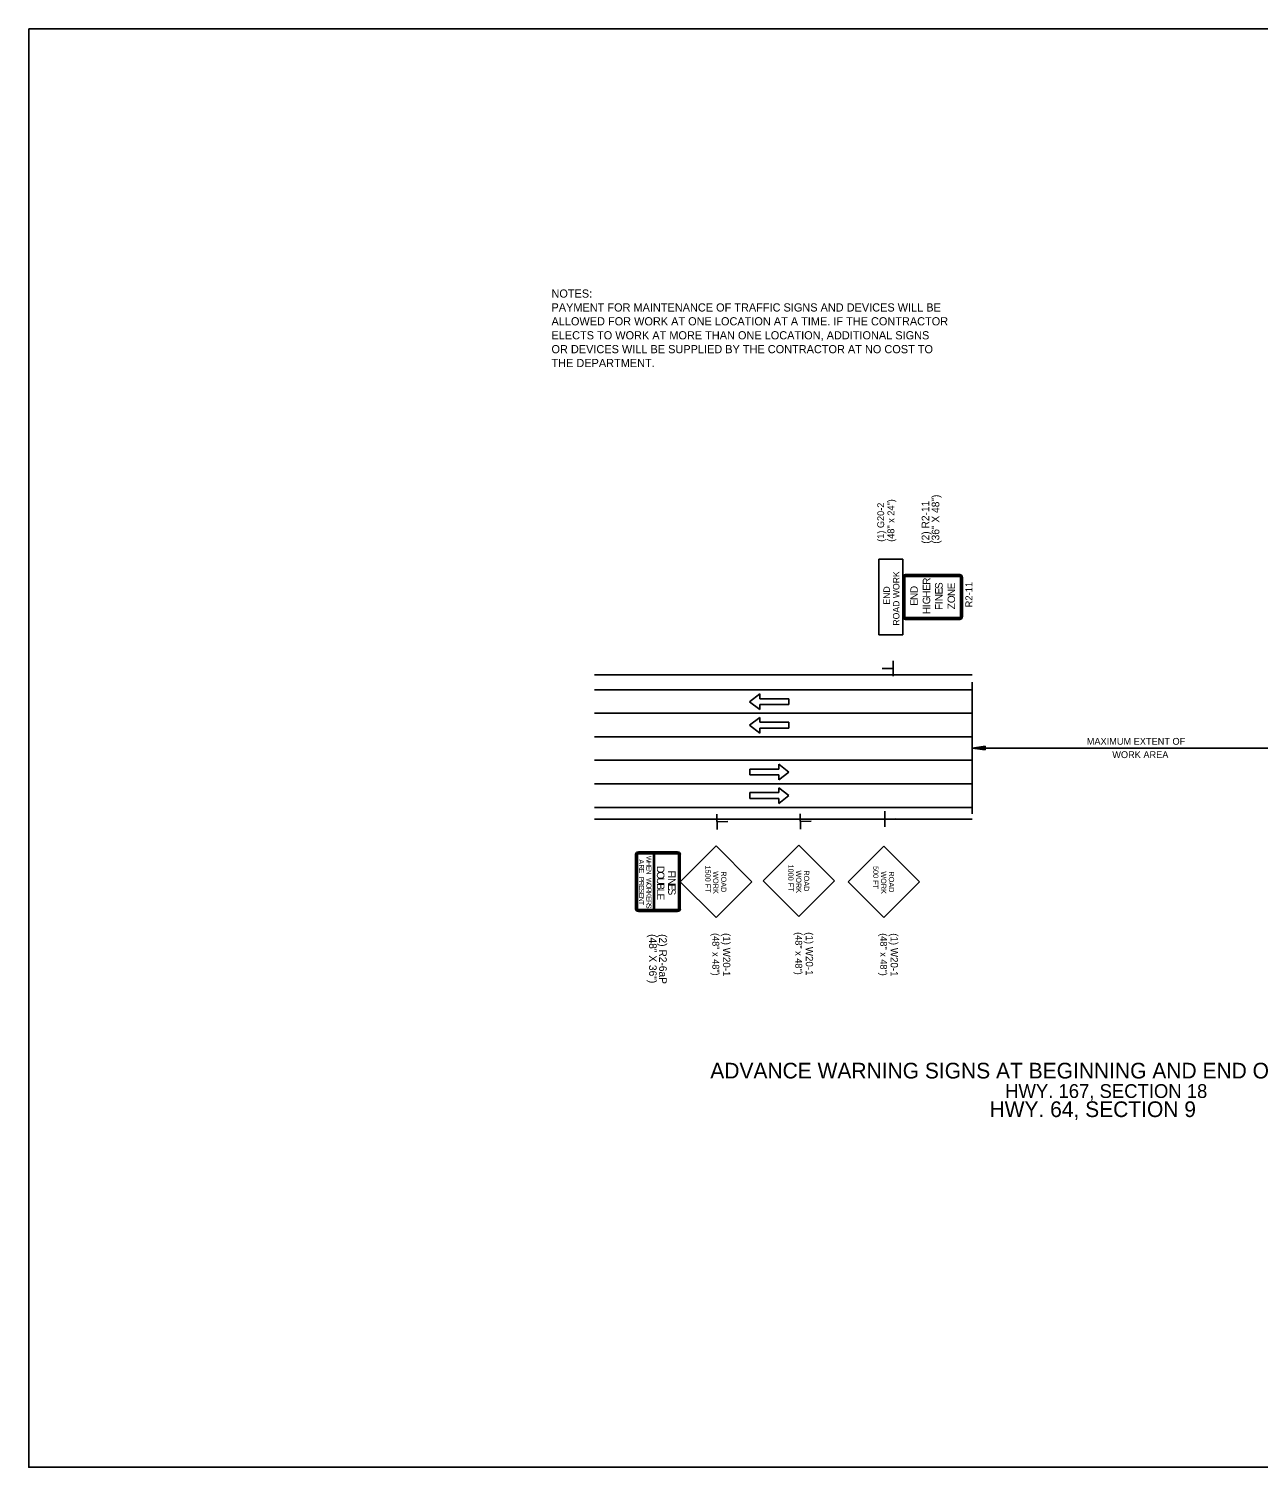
# Model space of a CAD drawing. Extents: x 32485 to 39285, y 55121 to 58033.
# Drawn here: x 37580 to 38520, y 55121 to 56221 of the extents above; entities that cross this region are included whole.
import ezdxf

# ---------------------------------------------------------------- set-up
doc = ezdxf.new("R2010")
doc.units = 0
for name, color, linetype in [('Default', 7, 'Continuous'), ('DSN_DRFT_Junk-No-Plot', 7, 'Continuous'), ('R_Border', 7, 'Continuous'), ('R_Draft', 7, 'Continuous'), ('R_Exist Surface', 7, 'Continuous')]:
    doc.layers.add(name, color=color, linetype=linetype)

msp = doc.modelspace()

# ---------------------------------------------------------------- linework, layer by layer
at = {"layer": 'Default'}
for p, q in [((38291.6, 55803.4), (38250.2, 55803.4)), ((38248, 55801.2), (38248, 55771.2)), ((38248.6, 55801.2), (38248.6, 55771.2)), ((38249.5, 55771.2), (38249.5, 55801.2)), ((38291.6, 55802.8), (38250.2, 55802.8)), ((38250.2, 55801.9), (38291.6, 55801.9)), ((38292.3, 55801.2), (38292.3, 55771.2)), ((38293.1, 55771.2), (38293.1, 55801.2)), ((38293.7, 55771.2), (38293.7, 55801.2)), ((38291.6, 55770.5), (38250.2, 55770.5)), ((38250.2, 55769.7), (38291.6, 55769.7)), ((38250.2, 55769.1), (38291.6, 55769.1)), ((38301, 55721), (38301, 55620.4)), ((38131, 55706.1), (38138.8, 55712.1)), ((38138.8, 55700.1), (38131, 55706.1)), ((38138.8, 55708.4), (38138.8, 55712.1)), ((38138.8, 55708.4), (38160.9, 55708.4)), ((38160.9, 55703.9), (38160.9, 55708.4)), ((38131, 55688.1), (38138.8, 55694.1)), ((38138.8, 55703.9), (38160.9, 55703.9)), ((38138.8, 55700.1), (38138.8, 55703.9)), ((38138.8, 55690.4), (38138.8, 55694.1)), ((38138.8, 55682.1), (38131, 55688.1)), ((38138.8, 55690.4), (38160.9, 55690.4)), ((38138.8, 55685.9), (38160.9, 55685.9)), ((38138.8, 55682.1), (38138.8, 55685.9)), ((38160.9, 55685.9), (38160.9, 55690.4)), ((38301, 55670.7), (38558.8, 55670.7)), ((38357.1, 55670.7), (38502.8, 55670.7)), ((38153.2, 55654.6), (38131.2, 55654.6)), ((38131.2, 55654.6), (38131.2, 55650.1)), ((38153.2, 55650.1), (38131.2, 55650.1)), ((38153.2, 55658.3), (38153.2, 55654.6)), ((38153.2, 55658.3), (38161, 55652.3)), ((38161, 55652.3), (38153.2, 55646.3)), ((38153.2, 55650.1), (38153.2, 55646.3)), ((38153.2, 55640.3), (38153.2, 55636.6)), ((38153.2, 55640.3), (38161, 55634.3)), ((38153.2, 55636.6), (38131.2, 55636.6)), ((38131.2, 55636.6), (38131.2, 55632.1)), ((38153.2, 55632.1), (38131.2, 55632.1)), ((38161, 55634.3), (38153.2, 55628.3)), ((38153.2, 55632.1), (38153.2, 55628.3)), ((38043.8, 55589.2), (38043.8, 55547.8)), ((38044.4, 55589.2), (38044.4, 55547.8)), ((38045.2, 55547.8), (38045.2, 55589.2)), ((38075.9, 55591.3), (38045.9, 55591.3)), ((38075.9, 55590.7), (38045.9, 55590.7)), ((38045.9, 55589.9), (38075.9, 55589.9)), ((38057.4, 55547.1), (38057.4, 55589.9)), ((38057.4, 55589.9), (38058.2, 55589.9)), ((38058.2, 55589.9), (38058.2, 55547.1)), ((38076.6, 55589.2), (38076.6, 55547.8)), ((38077.4, 55547.8), (38077.4, 55589.2)), ((38078, 55547.8), (38078, 55589.2)), ((38075.9, 55547.1), (38045.9, 55547.1)), ((38045.9, 55546.2), (38075.9, 55546.2)), ((38045.9, 55545.6), (38075.9, 55545.6)), ((38058.2, 55547.1), (38057.4, 55547.1))]:
    msp.add_line(p, q, dxfattribs=at)
msp.add_lwpolyline([(37579.9, 56220.7), (37579.9, 55120.7), (39279.9, 55120.7), (39279.9, 56220.7)], close=True, dxfattribs=at)
for centre, radius, start, end in [((38250.2, 55801.2), 2.14, 90, 180), ((38291.6, 55801.2), 2.14, 0, 90), ((38250.2, 55801.2), 1.55, 90, 180), ((38250.2, 55801.2), 0.714, 90, 180), ((38291.6, 55801.2), 1.55, 0, 90), ((38291.6, 55801.2), 0.714, 0, 90), ((38250.2, 55771.2), 2.14, 180, 270), ((38250.2, 55771.2), 1.55, 180, 270), ((38250.2, 55771.2), 0.714, 180, 270), ((38291.6, 55771.2), 2.14, 270, 0), ((38291.6, 55771.2), 1.55, 270, 0), ((38291.6, 55771.2), 0.714, 270, 0), ((38045.9, 55589.2), 2.14, 90, 180), ((38045.9, 55589.2), 1.55, 90, 180), ((38045.9, 55589.2), 0.714, 90, 180), ((38075.9, 55589.2), 2.14, 0, 90), ((38075.9, 55589.2), 1.55, 0, 90), ((38075.9, 55589.2), 0.714, 0, 90), ((38045.9, 55547.8), 2.14, 180, 270), ((38045.9, 55547.8), 1.55, 180, 270), ((38045.9, 55547.8), 0.714, 180, 270), ((38075.9, 55547.8), 2.14, 270, 0), ((38075.9, 55547.8), 1.55, 270, 0), ((38075.9, 55547.8), 0.714, 270, 0)]:
    msp.add_arc(centre, radius, start, end, dxfattribs=at)
at = {"layer": 'DSN_DRFT_Junk-No-Plot'}
msp.add_lwpolyline([(37579.9, 56220.7), (39279.9, 56220.7), (39279.9, 55120.7), (37579.9, 55120.7)], close=True, dxfattribs=at)
at = {"layer": 'R_Border'}
for p, q in [((38229.8, 55815.2), (38229.8, 55757.3)), ((38248, 55815.2), (38229.8, 55815.2)), ((38248, 55815.2), (38248, 55757.3)), ((38248, 55757.3), (38229.8, 55757.3)), ((38240.6, 55737.4), (38240.6, 55725.6)), ((38240.4, 55731.6), (38232.4, 55731.5)), ((38106.1, 55608.4), (38105.9, 55620.1)), ((38169.8, 55608.7), (38169.6, 55620.4)), ((38234.4, 55610.5), (38234.3, 55622.3)), ((38234.5, 55616.4), (38242.6, 55616.5)), ((38106.2, 55614.2), (38114.2, 55614.4)), ((38169.8, 55614.5), (38177.9, 55614.7)), ((38078, 55568.5), (38105.3, 55595.8)), ((38132.6, 55568.5), (38105.3, 55595.8)), ((38141.4, 55569.2), (38168.6, 55596.5)), ((38195.9, 55569.2), (38168.6, 55596.5)), ((38206.3, 55568.4), (38233.5, 55595.7)), ((38260.8, 55568.4), (38233.5, 55595.7)), ((38105.3, 55541.2), (38078, 55568.5)), ((38105.3, 55541.2), (38132.6, 55568.5)), ((38168.6, 55541.9), (38141.4, 55569.2)), ((38168.6, 55541.9), (38195.9, 55569.2)), ((38233.5, 55541.1), (38206.3, 55568.4)), ((38233.5, 55541.1), (38260.8, 55568.4))]:
    msp.add_line(p, q, dxfattribs=at)
at = {"layer": 'R_Draft'}
for p, q in [((38311, 55672.2), (38301, 55670.7)), ((38311, 55672), (38302.7, 55670.7)), ((38311, 55671.7), (38304.4, 55670.7)), ((38311, 55671.5), (38306.1, 55670.7)), ((38311, 55671.2), (38307.8, 55670.7)), ((38311, 55669.2), (38311, 55672.2)), ((38311, 55669.2), (38301, 55670.7)), ((38311, 55669.5), (38302.7, 55670.7)), ((38311, 55669.7), (38304.4, 55670.7)), ((38311, 55670), (38306.1, 55670.7)), ((38311, 55670.2), (38307.8, 55670.7)), ((38311, 55671), (38309.5, 55670.7)), ((38311, 55670.5), (38309.5, 55670.7))]:
    msp.add_line(p, q, dxfattribs=at)
at = {"layer": 'R_Exist Surface'}
for p, q in [((38012.3, 55726.8), (38301, 55726.8)), ((38012.3, 55715.3), (38301, 55715.3)), ((38012.3, 55697.3), (38301, 55697.3)), ((38012.3, 55679.3), (38301, 55679.3)), ((38012.3, 55661.3), (38301, 55661.3)), ((38012.3, 55643.3), (38301, 55643.3)), ((38012.3, 55625.3), (38301, 55625.3)), ((38012.3, 55616.3), (38301, 55616.3))]:
    msp.add_line(p, q, dxfattribs=at)

# ---------------------------------------------------------------- texts
at = {"layer": 'Default'}
for s, height, p in [('NOTES: ', 6.25, (37979.5, 56015.1)), ('PAYMENT FOR MAINTENANCE OF TRAFFIC SIGNS AND DEVICES WILL BE ', 6.25, (37979.5, 56004.5)), ('ALLOWED FOR WORK AT ONE LOCATION AT A TIME. IF THE CONTRACTOR', 6.25, (37979.5, 55993.9)), ('ELECTS TO WORK AT MORE THAN ONE LOCATION, ADDITIONAL SIGNS', 6.25, (37979.5, 55983.2)), ('THE DEPARTMENT.', 6.25, (37979.5, 55962)), ('OR DEVICES WILL BE SUPPLIED BY THE CONTRACTOR AT NO COST TO ', 6.25, (37979.5, 55972.6)), ('MAXIMUM EXTENT OF ', 5.25, (38388.7, 55673.2)), ('WORK AREA', 5.25, (38408.2, 55663)), ('ADVANCE WARNING SIGNS AT BEGINNING AND END OF WORK ZONE', 12, (38100.9, 55418)), ('HWY. 167, SECTION 18', 10.557, (38326.3, 55403.1)), (' HWY. 64, SECTION 9 ', 12, (38309.9, 55388.5))]:
    msp.add_text(s, height=height, dxfattribs=at).set_placement(p)
for s, height, rotation, p in [('D', 5.71, 90, (38259.5, 55789.2)), ('R', 5.71, 90, (38269, 55795.5)), ('E', 5.71, 90, (38269, 55791)), ('S', 5.71, 90, (38278.5, 55792.3)), ('E', 5.71, 90, (38278.5, 55788.2)), ('E', 5.71, 90, (38288, 55792.1)), ('R2-11', 5.38, 90, (38301.3, 55778.2)), ('N', 5.71, 90, (38259.5, 55783.9)), ('E', 5.71, 90, (38259.5, 55779.4)), ('G', 5.71, 90, (38269, 55780.6)), ('H', 5.71, 90, (38269, 55785.7)), ('N', 5.71, 90, (38278.5, 55783)), ('I', 5.71, 90, (38278.5, 55780.7)), ('O', 5.71, 90, (38288, 55781.5)), ('N', 5.71, 90, (38288, 55786.9)), ('Z', 5.71, 90, (38288, 55776.8)), ('I', 5.71, 90, (38269, 55778.4)), ('H', 5.71, 90, (38269, 55773.1)), ('F', 5.71, 90, (38278.5, 55776.3)), ('A', 3.81, 270, (38046.4, 55585.5)), ('W', 3.81, 270, (38052.1, 55588.2)), ('H', 3.81, 270, (38052.1, 55584.2)), ('R', 3.81, 270, (38046.4, 55581.7)), ('E', 3.81, 270, (38046.4, 55578.5)), ('E', 3.81, 270, (38052.1, 55580.7)), ('N', 3.81, 270, (38052.1, 55577.7)), ('O', 5.71, 270, (38060.1, 55576.3)), ('D', 5.71, 270, (38060.1, 55580.5)), ('F', 5.71, 270, (38068.7, 55577)), ('I', 5.71, 270, (38068.7, 55573.3)), ('P', 3.81, 270, (38046.4, 55572.3)), ('R', 3.81, 270, (38046.4, 55569.2)), ('E', 3.81, 270, (38046.4, 55565.9)), ('S', 3.81, 270, (38046.4, 55563.2)), ('W', 3.81, 270, (38052.1, 55571.3)), ('O', 3.81, 270, (38052.1, 55567.4)), ('R', 3.81, 270, (38052.1, 55563.9)), ('U', 5.71, 270, (38060.1, 55571.7)), ('B', 5.71, 270, (38060.1, 55567.3)), ('L', 5.71, 270, (38060.1, 55563.1)), ('S', 5.71, 270, (38068.7, 55563.2)), ('N', 5.71, 270, (38068.7, 55571.2)), ('E', 5.71, 270, (38068.7, 55566.8)), ('E', 3.81, 270, (38046.4, 55560)), ('N', 3.81, 270, (38046.4, 55557)), ('T', 3.81, 270, (38046.4, 55553.8)), ('K', 3.81, 270, (38052.1, 55560.7)), ('E', 3.81, 270, (38052.1, 55557.4)), ('R', 3.81, 270, (38052.1, 55554.3)), ('S', 3.81, 270, (38052.1, 55551.4)), ('E', 5.71, 270, (38060.1, 55559.4))]:
    msp.add_text(s, height=height, rotation=rotation, dxfattribs=at).set_placement(p)
at = {"layer": 'R_Border'}
for s, height, rotation, p in [('(48" x 24")', 5.233, 90, (38241.6, 55828.4)), ('(1) G20-2', 5.23, 90, (38233.8, 55828.4)), ('ROAD WORK', 4.95, 90, (38245.5, 55764.3)), ('END', 4.95, 90, (38238.2, 55780.4)), ('1500 FT', 4.02, 270.0006, (38097.1, 55580.8)), ('WORK', 4.02, 270, (38103.1, 55576.5)), ('ROAD', 4.02, 270.0004, (38109.2, 55576.4)), ('1000 FT', 4.02, 270.0006, (38160.5, 55581.6)), ('WORK', 4.02, 270, (38166.5, 55577.1)), ('ROAD', 4.02, 270.0004, (38172.5, 55577.1)), (' 500 FT', 4.02, 270.0006, (38225.4, 55582)), ('WORK', 4.02, 270, (38231.4, 55576.4)), ('ROAD', 4.02, 270.0004, (38237.4, 55576.3)), ('(48" x 48")', 5.233, 270, (38102.5, 55529.2)), ('(1) W20-1', 5.58, 270, (38110.6, 55529.2)), ('(48" x 48")', 5.233, 270, (38165.9, 55529.9)), ('(1) W20-1', 5.58, 270, (38173.9, 55529.9)), ('(48" x 48")', 5.233, 270, (38230.8, 55529.1)), ('(1) W20-1', 5.58, 270, (38238.8, 55529.1))]:
    msp.add_text(s, height=height, rotation=rotation, dxfattribs=at).set_placement(p)
at = {"layer": 'R_Draft'}
for s, rotation, p in [('(2) R2-11', 90, (38268.3, 55826.9)), ('(36" X 48")', 90, (38276, 55826.9)), ('(48" X 36")', 270, (38054.1, 55528.4)), ('(2) R2-6aP', 270, (38061.8, 55528.4))]:
    msp.add_text(s, height=5.83, rotation=rotation, dxfattribs=at).set_placement(p)

doc.saveas('drawing.dxf')
